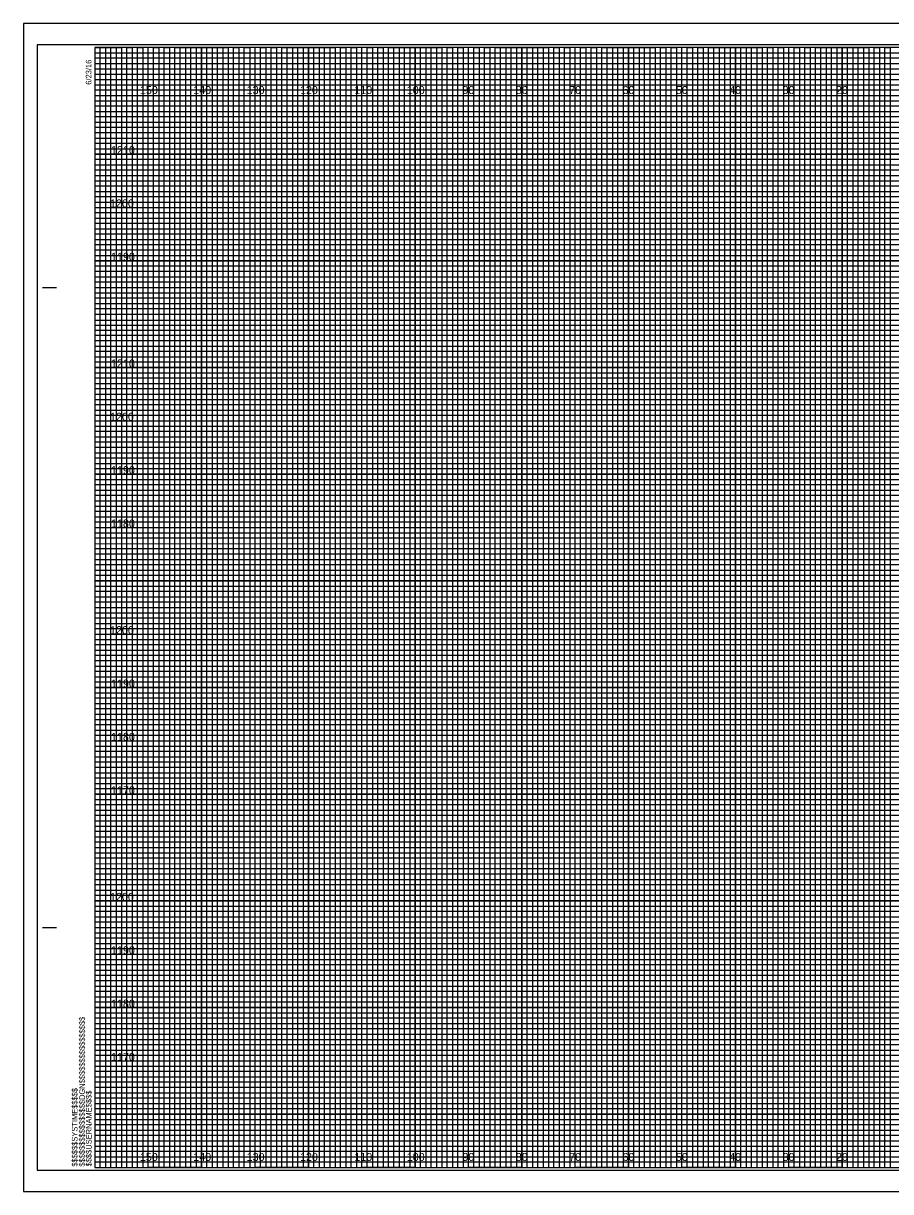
# Model space of a CAD drawing. Extents: x -13 to 323, y 1976 to 2194.
# Drawn here: x -13.4 to 149.1, y 1975.5 to 2194.5 of the extents above; entities that cross this region are included whole.
import ezdxf

# ---------------------------------------------------------------- set-up
doc = ezdxf.new("R2010")
doc.units = 0
for name, color, linetype in [('Prop XS Elevation Labels', 7, 'Continuous'), ('Prop XS Offset Labels', 7, 'Continuous'), ('Sheet Cross Section CELL', 7, 'Continuous'), ('Sheet Cross Section Grid Major CELL', 7, 'Continuous'), ('Sheet Cross Section Grid Middle CELL', 7, 'Continuous'), ('Sheet Cross Section Grid Minor 1 CELL', 7, 'Continuous'), ('Sheet Cross Section Grid Minor 2 CELL', 7, 'Continuous'), ('Sheet Cutting Line CELL', 7, 'Continuous'), ('Sheet DOT Grid CELL', 7, 'Continuous'), ('Sheet Plot Border Inside CELL', 7, 'Continuous'), ('Sheet Plot Border Outside CELL', 7, 'Continuous')]:
    doc.layers.add(name, color=color, linetype=linetype)

msp = doc.modelspace()

# ---------------------------------------------------------------- linework, layer by layer
at = {"layer": 'Sheet Cross Section CELL'}
for p, q in [((-9.8, 2145), (-7.3, 2145)), ((-9.7, 2145), (-7.2, 2145)), ((-9.8, 2025), (-7.3, 2025)), ((-9.7, 2025), (-7.2, 2025)), ((0, 1980), (0, 1980)), ((0, 1980), (0, 1980)), ((0, 1980), (0, 1980)), ((0, 1980), (0, 1980)), ((0, 1980), (0, 1980)), ((0, 1980), (0, 1980)), ((0, 1980), (0, 1980))]:
    msp.add_line(p, q, dxfattribs=at)
msp.add_lwpolyline([(320, 2190), (0, 2190), (0, 1980), (320, 1980)], close=True, dxfattribs=at)
at = {"layer": 'Sheet Cross Section Grid Major CELL'}
for p, q in [((10, 2190), (0, 2190)), ((10, 1980), (10, 2190)), ((30, 2190), (20, 2190)), ((20, 2190), (20, 1980)), ((30, 1980), (30, 2190)), ((50, 2190), (40, 2190)), ((40, 2190), (40, 1980)), ((50, 1980), (50, 2190)), ((70, 2190), (60, 2190)), ((60, 2190), (60, 1980)), ((70, 1980), (70, 2190)), ((90, 2190), (80, 2190)), ((80, 2190), (80, 1980)), ((90, 1980), (90, 2190)), ((110, 2190), (100, 2190)), ((100, 2190), (100, 1980)), ((110, 1980), (110, 2190)), ((130, 2190), (120, 2190)), ((120, 2190), (120, 1980)), ((130, 1980), (130, 2190)), ((150, 2190), (140, 2190)), ((140, 2190), (140, 1980)), ((20, 1980), (10, 1980)), ((40, 1980), (30, 1980)), ((60, 1980), (50, 1980)), ((80, 1980), (70, 1980)), ((100, 1980), (90, 1980)), ((120, 1980), (110, 1980)), ((140, 1980), (130, 1980))]:
    msp.add_line(p, q, dxfattribs=at)
for points in [[(0, 2180), (320, 2180), (320, 2170), (0, 2170)], [(0, 2160), (320, 2160), (320, 2150), (0, 2150)], [(0, 2140), (320, 2140), (320, 2130), (0, 2130)], [(0, 2120), (320, 2120), (320, 2110), (0, 2110)], [(0, 2100), (320, 2100), (320, 2090), (0, 2090)], [(0, 2080), (320, 2080), (320, 2070), (0, 2070)], [(0, 2060), (320, 2060), (320, 2050), (0, 2050)], [(0, 2040), (320, 2040), (320, 2030), (0, 2030)], [(0, 2020), (320, 2020), (320, 2010), (0, 2010)], [(0, 2000), (320, 2000), (320, 1990), (0, 1990)]]:
    msp.add_lwpolyline(points, dxfattribs=at)
at = {"layer": 'Sheet Cross Section Grid Middle CELL'}
for points in [[(0, 2190), (5, 2190), (5, 1980), (15, 1980), (15, 2190), (25, 2190), (25, 1980), (35, 1980), (35, 2190), (45, 2190), (45, 1980), (55, 1980), (55, 2190), (65, 2190), (65, 1980), (75, 1980), (75, 2190), (85, 2190), (85, 1980), (95, 1980), (95, 2190), (105, 2190), (105, 1980), (115, 1980), (115, 2190), (125, 2190), (125, 1980), (135, 1980), (135, 2190), (145, 2190), (145, 1980), (155, 1980)], [(0, 2185), (275, 2185)], [(0, 2165), (320, 2165), (320, 2175), (0, 2175)], [(0, 2145), (320, 2145), (320, 2155), (0, 2155)], [(0, 2125), (320, 2125), (320, 2135), (0, 2135)], [(0, 2105), (320, 2105), (320, 2115), (0, 2115)], [(0, 2085), (320, 2085), (320, 2095), (0, 2095)], [(0, 2065), (320, 2065), (320, 2075), (0, 2075)], [(0, 2045), (320, 2045), (320, 2055), (0, 2055)], [(0, 2025), (320, 2025), (320, 2035), (0, 2035)], [(0, 2005), (320, 2005), (320, 2015), (0, 2015)], [(0, 1985), (320, 1985), (320, 1995), (0, 1995)]]:
    msp.add_lwpolyline(points, dxfattribs=at)
at = {"layer": 'Sheet Cross Section Grid Minor 1 CELL'}
for p, q in [((0, 2189), (260, 2189)), ((260, 2187.98), (0, 2187.98)), ((0, 2187.98), (0, 2187)), ((0, 2187), (260, 2187)), ((260, 2185.89), (0, 2185.89)), ((0, 2185.89), (0, 2184)), ((0, 2184), (320, 2184))]:
    msp.add_line(p, q, dxfattribs=at)
for points in [[(0, 2183), (270, 2183), (320, 2183), (320, 2182), (0, 2182)], [(0, 2181), (320, 2181), (320, 2179), (0, 2179)], [(0, 2178), (320, 2178), (320, 2177), (0, 2176.98)], [(0, 2176), (320, 2176), (320, 2174), (0, 2174)], [(0, 2173), (320, 2173), (320, 2172), (0, 2172)], [(0, 2171), (320, 2171), (320, 2169), (0, 2169)], [(0, 2168), (320, 2168), (320, 2167), (0, 2167)], [(0, 2166), (320, 2166), (320, 2164), (0, 2164)], [(0, 2163), (320, 2163), (320, 2162), (0, 2162)], [(0, 2161), (320, 2161), (320, 2159), (0, 2159)], [(0, 2158), (320, 2158), (320, 2157), (0, 2157)], [(0, 2156), (320, 2156), (320, 2153.95), (320, 2153), (320, 2152), (0, 2152)], [(0, 2154), (320, 2154), (320, 2153), (0, 2153)], [(0, 2151), (320, 2151), (320, 2149), (0, 2149.03)], [(0, 2149.03), (320, 2149), (320, 2148), (0, 2148)], [(0, 2147), (320, 2147), (320, 2146), (0, 2146)], [(0, 2144), (320, 2144), (320, 2143), (0, 2143)], [(0, 2142), (320, 2142), (320, 2141), (0, 2141)], [(-0.07, 2138.89), (320, 2138.89), (320, 2137.88), (-0.07, 2137.88)], [(0, 2137), (320, 2137), (320, 2136), (0, 2136)], [(0, 2134), (320, 2134), (320, 2133), (0, 2133)], [(0, 2132), (320, 2132), (320, 2131), (0, 2131)], [(0, 2129), (320, 2129), (320, 2128), (0, 2128)], [(0, 2127), (320, 2127), (320, 2126), (0, 2126)], [(0, 2124), (320, 2124), (320, 2123), (0, 2123)], [(0, 2122), (320, 2122), (320, 2121), (0, 2121)], [(0, 2119), (320, 2119), (319.99, 2117.98), (0, 2118)], [(0, 2117), (320, 2117), (320, 2116), (0, 2116)], [(0, 2114), (320, 2114), (320, 2113), (0, 2113)], [(0, 2112), (320, 2112), (320, 2111), (0, 2111)], [(0, 2109), (320, 2109), (320, 2108), (0, 2108)], [(0, 2107), (320, 2107), (320, 2106), (0, 2106)], [(0, 2104), (320, 2104), (320, 2103), (0, 2103)], [(0, 2102), (320, 2102), (320, 2101), (0, 2101)], [(0, 2099), (320, 2099), (320, 2098), (0, 2098)], [(0, 2096.99), (320.07, 2096.91), (320, 2096), (0, 2096)], [(0, 2094), (320, 2094), (320, 2093), (0, 2093)], [(0, 2092), (320, 2092), (320, 2091), (0, 2091)], [(0, 2089), (320, 2089), (320, 2088), (0, 2088)], [(0, 2087), (320, 2087), (320, 2086), (0, 2086)], [(0, 2084), (320, 2084), (320, 2083), (0, 2083)], [(0, 2082), (320, 2082), (320, 2081), (0, 2081)], [(0, 2079), (320, 2079), (320, 2078), (0, 2078)], [(0, 2077), (320, 2077), (320, 2076), (0, 2076)], [(0, 2074), (320, 2074), (320, 2073), (0, 2073)], [(0, 2072), (320, 2072), (320, 2071), (0, 2071)], [(0, 2069), (320, 2069), (320, 2068), (0, 2068)], [(0, 2067), (320, 2067), (320, 2066), (0, 2066)], [(0, 2064), (320, 2064), (320, 2063), (0, 2063)], [(0, 2062), (320, 2062), (320, 2061), (0, 2061)], [(0, 2059), (320, 2059), (319.99, 2057.98), (0, 2058)], [(0, 2057), (320, 2057), (320, 2056), (0, 2056)], [(0, 2054), (320, 2054), (320, 2053), (0, 2053)], [(0, 2052), (320, 2052), (320, 2051), (0, 2051)], [(0, 2049), (320, 2049), (320, 2048), (0, 2048)], [(0, 2047), (320, 2047), (320, 2046), (0, 2046)], [(0, 2044), (320, 2044), (320, 2043), (0, 2043)], [(0, 2042), (320, 2042), (320, 2041), (0, 2041)], [(0, 2039), (320, 2039), (320, 2038), (0, 2038)], [(0, 2036.99), (320.07, 2036.91), (320, 2036), (0, 2036)], [(0, 2034), (320, 2034), (320, 2033), (0, 2033)], [(0, 2032), (320, 2032), (320, 2031), (0, 2031)], [(0, 2029), (320, 2029), (320, 2028), (0, 2028)], [(0, 2027), (320, 2027), (320, 2026), (0, 2026)], [(0, 2024), (320, 2024), (320, 2023), (0, 2023)], [(0, 2022), (320, 2022), (320, 2021), (0, 2021)], [(0, 2019), (320, 2019), (320, 2018), (0, 2018)], [(0, 2017), (320, 2017), (320, 2016), (0, 2016)], [(0, 2014), (320, 2014), (320, 2013), (0, 2013)], [(0, 2012), (320, 2012), (320, 2011), (0, 2011)], [(0, 2009), (320, 2009), (320, 2008), (0, 2008)], [(0, 2007), (320, 2007), (320, 2006), (0, 2006)], [(0, 2004), (320, 2004), (320, 2003), (0, 2003)], [(0, 2002), (320, 2002), (320, 2001), (0, 2001)], [(0, 1999), (320, 1999), (320, 1998), (0, 1998)], [(0, 1997), (320, 1997), (320, 1996), (0, 1996)], [(0, 1994), (320, 1994), (320, 1993), (0, 1993)], [(0, 1992), (320, 1992), (320, 1991), (0, 1991)], [(0, 1989), (320, 1989), (320, 1988), (0, 1988)], [(0, 1987), (320, 1987), (320, 1986), (0, 1986)], [(0, 1984), (320, 1984), (320, 1983), (0, 1983)], [(0, 1982), (320, 1982), (320, 1981), (0, 1981)]]:
    msp.add_lwpolyline(points, dxfattribs=at)
at = {"layer": 'Sheet Cross Section Grid Minor 2 CELL'}
for points in [[(0, 1980), (1, 1980), (1, 2190), (2, 2190), (2, 1980)], [(2, 1980), (3, 1980), (3, 2190), (4, 2190), (4, 1980)], [(5, 1980), (6, 1980), (6, 2190), (7, 2190), (7, 1980)], [(7, 1980), (8, 1980), (8, 2190), (9, 2190), (9, 1980)], [(10, 1980), (11, 1980), (11, 2190), (12, 2190), (12, 1980)], [(12, 1980), (13, 1980), (13, 2190), (14, 2190), (14, 1980)], [(15, 1980), (16, 1980), (16, 2190), (17, 2190), (17, 1980)], [(17, 1980), (18, 1980), (18, 2190), (19, 2190), (19, 1980)], [(20, 1980), (21, 1980), (21, 2190), (22, 2190), (22, 1980)], [(22, 1980), (23, 1980), (23, 2190), (24, 2190), (24, 1980)], [(25, 1980), (26, 1980), (26, 2190), (27, 2190), (27, 1980)], [(27, 1980), (28, 1980), (28, 2190), (29, 2190), (29, 1980)], [(30, 1980), (31, 1980), (31, 2190), (32, 2190), (32, 1980)], [(32, 1980), (33, 1980), (33, 2190), (34, 2190), (34, 1980)], [(35, 1980), (36, 1980), (36, 2190), (37, 2190), (37, 1980)], [(37, 1980), (38, 1980), (38, 2190), (39, 2190), (39, 1980)], [(40, 1980), (41, 1980), (41, 2190), (42, 2190), (42, 1980)], [(42, 1980), (43, 1980), (43, 2190), (44, 2190), (44, 1980)], [(45, 1980), (46, 1980), (46, 2190), (47, 2190), (47, 1980)], [(47, 1980), (48, 1980), (48, 2190), (49, 2190), (49, 1980)], [(50, 1980), (51, 1980), (51, 2190), (52, 2190), (52, 1980)], [(52, 1980), (53, 1980), (53, 2190), (54, 2190), (54, 1980)], [(55, 1980), (56, 1980), (56, 2190), (57, 2190), (57, 1980)], [(57, 1980), (58, 1980), (58, 2190), (59, 2190), (59, 1980)], [(60, 1980), (61, 1980), (61, 2190), (62, 2190), (62, 1980)], [(62, 1980), (63, 1980), (63, 2190), (64, 2190), (64, 1980)], [(65, 1980), (66, 1980), (66, 2190), (67, 2190), (67, 1980)], [(67, 1980), (68, 1980), (68, 2190), (69, 2190), (69, 1980)], [(70, 1980), (71, 1980), (71, 2190), (72, 2190), (72, 1980)], [(72, 1980), (73, 1980), (73, 2190), (74, 2190), (74, 1980)], [(75, 1980), (76, 1980), (76, 2190), (77, 2190), (77, 1980)], [(77, 1980), (78, 1980), (78, 2190), (79, 2190), (79, 1980)], [(80, 1980), (81, 1980), (81, 2190), (82, 2190), (82, 1980)], [(82, 1980), (83, 1980), (83, 2190), (84, 2190), (84, 1980)], [(85, 1980), (86, 1980), (86, 2190), (87, 2190), (87, 1980)], [(87, 1980), (88, 1980), (88, 2190), (89, 2190), (89, 1980)], [(90, 1980), (91, 1980), (91, 2190), (92, 2190), (92, 1980)], [(92, 1980), (93, 1980), (93, 2190), (94, 2190), (94, 1980)], [(95, 1980), (96, 1980), (96, 2190), (97, 2190), (97, 1980)], [(97, 1980), (98, 1980), (98, 2190), (99, 2190), (99, 1980)], [(100, 1980), (101, 1980), (101, 2190), (102, 2190), (102, 1980)], [(102, 1980), (103, 1980), (103, 2190), (104, 2190), (104, 1980)], [(105, 1980), (106, 1980), (106, 2190), (107, 2190), (107, 1980)], [(107, 1980), (108, 1980), (108, 2190), (109, 2190), (109, 1980)], [(110, 1980), (111, 1980), (111, 2190), (112, 2190), (112, 1980)], [(112, 1980), (113, 1980), (113, 2190), (114, 2190), (114, 1980)], [(115, 1980), (116, 1980), (116, 2190), (117, 2190), (117, 1980)], [(117, 1980), (118, 1980), (118, 2190), (119, 2190), (119, 1980)], [(120, 1980), (121, 1980), (121, 2190), (122, 2190), (122, 1980)], [(122, 1980), (123, 1980), (123, 2190), (124, 2190), (124, 1980)], [(125, 1980), (126, 1980), (126, 2190), (127, 2190), (127, 1980)], [(127, 1980), (128, 1980), (128, 2190), (129, 2190), (129, 1980)], [(130, 1980), (131, 1980), (131, 2190), (132, 2190), (132, 1980)], [(132, 1980), (133, 1980), (133, 2190), (134, 2190), (134, 1980)], [(135, 1980), (136, 1980), (136, 2190), (137, 2190), (137, 1980)], [(137, 1980), (138, 1980), (138, 2190), (139, 2190), (139, 1980)], [(140, 1980), (141, 1980), (141, 2190), (142, 2190), (142, 1980)], [(142, 1980), (143, 1980), (143, 2190), (144, 2190), (144, 1980)], [(145, 1980), (146, 1980), (146, 2190), (147, 2190), (147, 1980)], [(147, 1980), (148, 1980), (148, 2190), (149, 2190), (149, 1980)]]:
    msp.add_lwpolyline(points, dxfattribs=at)
at = {"layer": 'Sheet Cutting Line CELL'}
for p, q in [((323.3, 2194.5), (-13.4, 2194.5)), ((-13.4, 2194.5), (-13.4, 1975.5)), ((-13.4, 1975.5), (323.3, 1975.5))]:
    msp.add_line(p, q, dxfattribs=at)
at = {"layer": 'Sheet DOT Grid CELL'}
for p, q in [((10, 1980), (10, 2190)), ((20, 1980), (20, 2190)), ((30, 1980), (30, 2190)), ((40, 1980), (40, 2190)), ((50, 1980), (50, 2190)), ((60, 1980), (60, 2190)), ((70, 1980), (70, 2190)), ((80, 1980), (80, 2190)), ((90, 1980), (90, 2190)), ((100, 1980), (100, 2190)), ((110, 1980), (110, 2190)), ((120, 1980), (120, 2190)), ((130, 1980), (130, 2190)), ((140, 1980), (140, 2190)), ((0, 2180), (320, 2180)), ((0, 2170), (320, 2170)), ((0, 2160), (320, 2160)), ((0, 2150), (320, 2150)), ((0, 2140), (320, 2140)), ((0, 2130), (320, 2130)), ((0, 2120), (320, 2120)), ((0, 2110), (320, 2110)), ((0, 2100), (320, 2100)), ((0, 2090), (320, 2090)), ((0, 2080), (320, 2080)), ((0, 2070), (320, 2070)), ((0, 2060), (320, 2060)), ((0, 2050), (320, 2050)), ((0, 2040), (320, 2040)), ((0, 2030), (320, 2030)), ((0, 2020), (320, 2020)), ((0, 2010), (320, 2010)), ((0, 2000), (320, 2000)), ((0, 1990), (320, 1990))]:
    msp.add_line(p, q, dxfattribs=at)
at = {"layer": 'Sheet Plot Border Inside CELL'}
msp.add_lwpolyline([(-10.8, 1979.5), (322.4, 1979.5), (322.4, 2190.5), (-10.8, 2190.5)], close=True, dxfattribs=at)
at = {"layer": 'Sheet Plot Border Outside CELL'}
msp.add_lwpolyline([(-13.4, 1975.5), (323.3, 1975.5), (323.3, 2194.5), (-13.4, 2194.5)], close=True, dxfattribs=at)

# ---------------------------------------------------------------- texts
at = {"layer": 'Prop XS Elevation Labels'}
for s, p in [('1210', (3.03, 2170)), ('1200', (2.85, 2160)), ('1190', (3.03, 2150)), ('1210', (3.03, 2130)), ('1200', (2.85, 2120)), ('1190', (3.03, 2110)), ('1180', (3.03, 2100)), ('1200', (2.85, 2080)), ('1190', (3.03, 2070)), ('1180', (3.03, 2060)), ('1170', (3.03, 2050)), ('1200', (2.85, 2030)), ('1190', (3.03, 2020)), ('1180', (3.03, 2010)), ('1170', (3.03, 2000))]:
    msp.add_text(s, height=1.5, dxfattribs=at).set_placement(p)
at = {"layer": 'Prop XS Offset Labels'}
for s, p in [('150', (8.44, 2181.25)), ('140', (18.44, 2181.25)), ('130', (28.44, 2181.25)), ('120', (38.44, 2181.25)), ('110', (48.62, 2181.25)), ('100', (58.44, 2181.25)), ('90', (68.86, 2181.25)), ('80', (78.86, 2181.25)), ('70', (88.86, 2181.25)), ('60', (98.86, 2181.25)), ('50', (108.86, 2181.25)), ('40', (118.86, 2181.25)), ('30', (128.86, 2181.25)), ('20', (138.86, 2181.25)), ('150', (8.44, 1981.25)), ('140', (18.44, 1981.25)), ('130', (28.44, 1981.25)), ('120', (38.44, 1981.25)), ('110', (48.62, 1981.25)), ('100', (58.44, 1981.25)), ('90', (68.86, 1981.25)), ('80', (78.86, 1981.25)), ('70', (88.86, 1981.25)), ('60', (98.86, 1981.25)), ('50', (108.86, 1981.25)), ('40', (118.86, 1981.25)), ('30', (128.86, 1981.25)), ('20', (138.86, 1981.25))]:
    msp.add_text(s, height=1.5, dxfattribs=at).set_placement(p)
at = {"layer": 'Sheet Cross Section CELL'}
for s, p in [('6/23/16', (-0.65, 2183)), ('$$$$$$$$$$$$$$$$DGN$$$$$$$$$$$$$$$$', (-1.88, 1980.18)), ('$$$$$$SYSTIME$$$$$', (-3.26, 1980.18)), ('$$$$USERNAME$$$$', (-0.62, 1980.23))]:
    msp.add_text(s, height=1.05, rotation=90, dxfattribs=at).set_placement(p)

doc.saveas('drawing.dxf')
